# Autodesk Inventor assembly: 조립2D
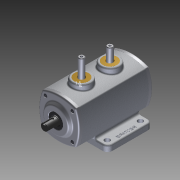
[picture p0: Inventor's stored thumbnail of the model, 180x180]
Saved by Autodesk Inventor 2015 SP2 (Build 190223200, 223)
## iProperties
Created: 2015-06
Part Number: 조립2D
Document SubType Name: Assembly
Designer: AMC
Author: AMC
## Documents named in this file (12)
- C:\Users\AMC\Desktop\350620V1009\조립2D.iam
- C:\Users\AMC\Desktop\350620V1009\M4-소켓머리.ipt
- C:\Users\AMC\Desktop\350620V1009\뒷커버.ipt
- C:\Users\AMC\Desktop\350620V1009\베어링 6203.ipt
- C:\Users\AMC\Desktop\350620V1009\본체.ipt
- C:\Users\AMC\Desktop\350620V1009\부시.ipt
- C:\Users\AMC\Desktop\350620V1009\슬라이더.ipt
- C:\Users\AMC\Desktop\350620V1009\앞커버.ipt
- C:\Users\AMC\Desktop\350620V1009\오일실.ipt
- C:\Users\AMC\Desktop\350620V1009\축.ipt
- C:\Users\AMC\Desktop\350620V1009\스프링.ipt
- C:\Users\AMC\Desktop\350620V1009\스프링11.ipt
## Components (11 placed, 3 different names)
1. 7-베어링 6203:1
2. 8-오일실:1
3. 7-베어링 6203:2
4. 9-M4-소켓머리:1
5. 9-M4-소켓머리:3
6. 9-M4-소켓머리:4
7. 9-M4-소켓머리:5
8. 9-M4-소켓머리:2
9. 9-M4-소켓머리:6
10. 9-M4-소켓머리:7
11. 9-M4-소켓머리:8
